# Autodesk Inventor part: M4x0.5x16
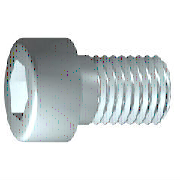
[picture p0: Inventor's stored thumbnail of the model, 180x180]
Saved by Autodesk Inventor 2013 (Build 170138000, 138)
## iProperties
Created: 2009-02
Part Number: M4x0.5x16
Material: 강, 연강
Description: 6각머리 태핑 나사
Document SubType Name: Modeling
Standard: KS B 1003
Designer: 한국산업디자인학원
Standards Organization: KS
Language: ko-KR
Size Designation: M 4 x 16
Categories: <MemberInstance><Categories><Category DisplayName="조임쇠" InternalName="e4da775c-781d-43d5-af7c-5136215cf5a6" Mnemonic="FSTN"><Category DisplayName="볼트" InternalN
Density: 1 g/cm^3
IsCustomPart: 1
Author: 한국산업디자인학원
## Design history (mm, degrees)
sketch "스케치1"
  geometry: L1 (-1, 0)-(16, 0); L2 (16, 0)-(16, 2); L3 (16, 2)-(1.75, 2); L4 (1.75, 2)-(1.32, 2); L5 (1.32, 2)-(0, 2); L6 (0, 2)-(0, 3.5); L7 (0, 3.5)-(-4, 3.5); L8 (-4, 3.5)-(-4, 1.732); L9 (-4, 1.732)-(-2, 1.732); L10 (-2, 1.732)-(-1, 0); L11 (-8, 0)-(20, 0) reference; L12 (0, -0.7)-(0, 4.2) reference; L13 (1.75, 2)-(0, 2)
  constraints: 22 end point, 6 parallel, 2 collinear, 2 perpendicular, 1 horizontal, 1 point on line
  dimensions: "d1" = 14.25 distance from line of L3.end L2 (= GEL); "d2" = 0.42952 distance of L4.end L3.end (computed from GAL); "d3" = 4 distance between parallel lines of L8 L6 (= KOH); "d4" = 2 distance of L8.end L9.end (= INTI); "d5" = 60 deg angle of L10 L1; "d6" = 4 diameter of L3 L1 (= GD); "d7" = 4 diameter of L5 L1 (= BDM); "d8" = 3.4641 diameter of L9 L1 (= 1.1547 x SW); "d9" = 7 diameter of L7 L1 (= KOD); "d26" = 16 distance between parallel lines of L12 L2 (= NLG)
revolve "본체" sketch "스케치1" stored, may be unused: angle "d10" = 90 deg
sketch "스케치2"
  geometry: L1 (0, -4.9)-(0, 4.9) reference; L2 (-4.9, 0)-(4.9, 0) reference; L3 (1.732, 0)-(0.866, -1.5); L4 (0.866, -1.5)-(-0.866, -1.5); L5 (-0.866, -1.5)-(-1.732, 0); L6 (-1.732, 0)-(-0.866, 1.5); L7 (-0.866, 1.5)-(0.866, 1.5); L8 (0.866, 1.5)-(1.732, 0); 2 further points
  constraints: 12 end point, 1 coincident, 1 horizontal alignment, 1 point on line, 12 other
extrude "슬롯" join sketch "스케치2" stored distance "d11" = 10; taper "d12" = 0 deg
workplane "Work Plane1"
fillet "Fillet2" dims "d30" = 0.1 (= R)
body "Solid1"
fillet "모깎기1" dims "d17" = 0.4 (= RR)
feature "스레드" dims "d13" = 14.25 (= GEL), "d14" = 0
chamfer "모따기1" distance "d15" = 0.42941 (= -0.5 x SPD + 0.5 x GD); stored, may be unused: second distance "d16" = 0.42941 (= GUL), angle "d27" = 45 deg
other parameters: "GD" = 4 (= NND) [user parameter; used in 2 equation terms], "NLG" = 16 [user parameter; used in 1 equation term], "GEL" = 14.25 [user parameter; used in 2 equation terms], "KOD" = 7 [user parameter; used in 1 equation term], "KOH" = 4 [user parameter; used in 1 equation term], "INTI" = 2 [user parameter; used in 1 equation term], "GAL" = 0.42941 (= 0.61345 x PTC) [user parameter; used in 1 equation term], "GUL" = 0.42941 (= 0.61345 x PTC) [user parameter; used in 1 equation term], "BDM" = 4 (= NND) [user parameter; used in 1 equation term], "SW" = 3 [user parameter; used in 2 equation terms], "RR" = 0.4 [user parameter; used in 1 equation term], "SPD" = 3.14117 (= NND - 1.2269 x PTC) [user parameter; used in 1 equation term], "d19" = 0, "d28" = 0, "d29" = 0, "R" = 0.1 [user parameter; used in 1 equation term], "PHH" = 0.2 [user parameter], "GD1" = 3.14117 (= THREADDIA - 1.2269 x PTC) [user parameter], "THREADDIA" = 4 [user parameter; used in 1 equation term], "FAWI" = 45 deg [user parameter], "TPU" = 14.28571 (computed from PTC) [user parameter], "PTC" = 0.7 [user parameter; used in 5 equation terms], "NND" = 4 [user parameter; used in 3 equation terms], "TOA" = 30 deg [user parameter], "E0" = 3.465 (= 1.155 x SW) [user parameter]
